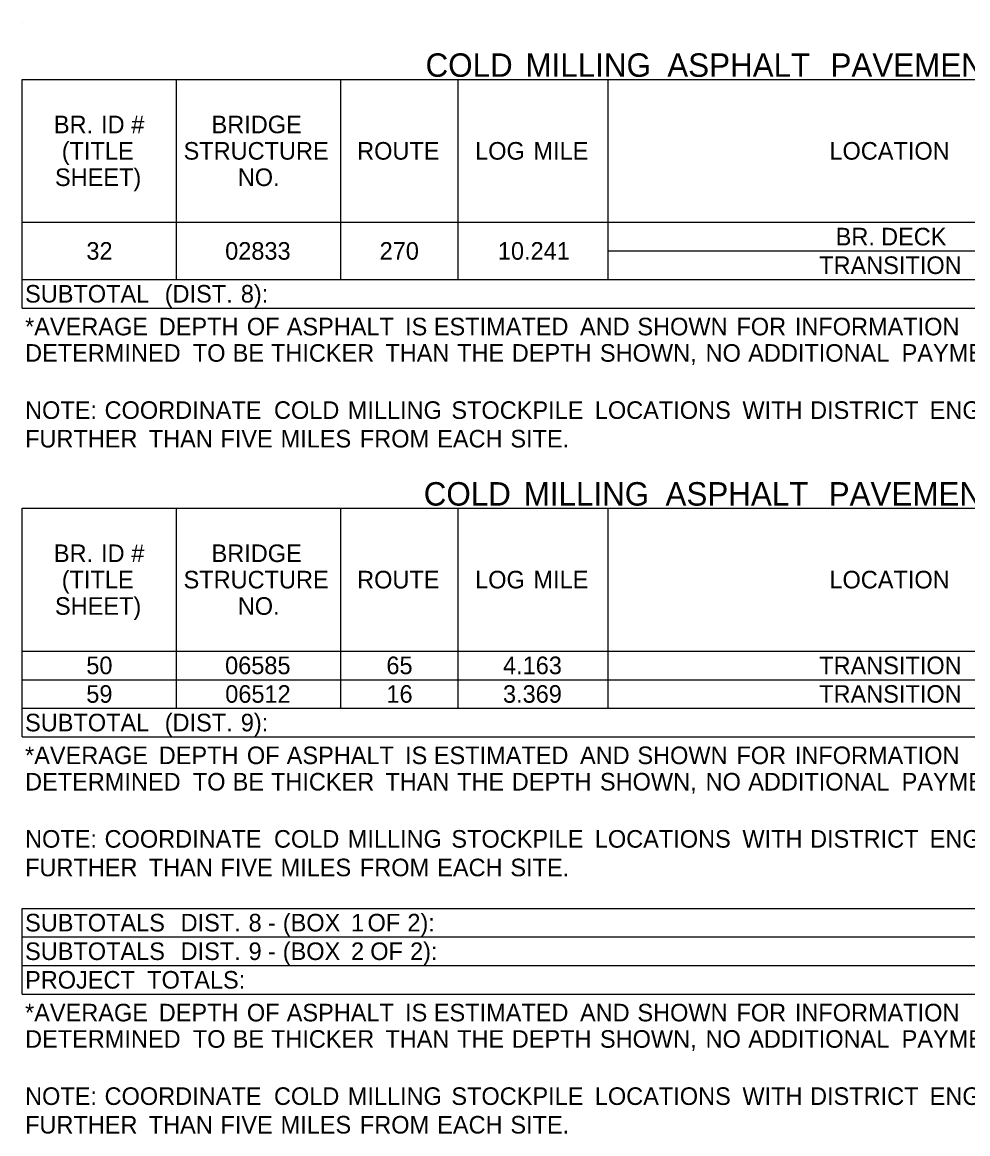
# Model space of a CAD drawing. Extents: x 544420 to 1930787, y -1947044 to 596640.
# Drawn here: x 546578.5 to 546901.1, y -1946424.4 to -1946045.3 of the extents above; entities that cross this region are included whole.
import ezdxf

# ---------------------------------------------------------------- set-up
doc = ezdxf.new("R2010")
doc.units = 0
doc.layers.add('Default', color=7, linetype='Continuous')

msp = doc.modelspace()

# ---------------------------------------------------------------- linework, layer by layer
at = {"layer": 'Default'}
for p, q in [((546578.54, -1946045.29), (546578.54, -1946045.29)), ((546578.54, -1946064.79), (547169.39, -1946064.79)), ((546578.54, -1946064.79), (547169.39, -1946064.79)), ((546578.54, -1946142.79), (546578.54, -1946064.79)), ((546631.19, -1946133.04), (546631.19, -1946064.79)), ((546687.25, -1946133.04), (546687.25, -1946064.79)), ((546727.23, -1946133.04), (546727.23, -1946064.79)), ((546778.41, -1946133.04), (546778.41, -1946064.79)), ((546578.54, -1946113.54), (547169.39, -1946113.54)), ((546578.54, -1946113.54), (546778.41, -1946113.54)), ((546778.41, -1946123.29), (547169.39, -1946123.29)), ((546578.54, -1946133.04), (547169.39, -1946133.04)), ((546578.54, -1946133.04), (547169.39, -1946133.04)), ((546578.54, -1946142.79), (547169.39, -1946142.79)), ((546578.54, -1946211.04), (547169.39, -1946211.04)), ((546578.54, -1946211.04), (547169.39, -1946211.04)), ((546578.54, -1946289.04), (546578.54, -1946211.04)), ((546631.19, -1946279.29), (546631.19, -1946211.04)), ((546687.25, -1946279.29), (546687.25, -1946211.04)), ((546727.23, -1946279.29), (546727.23, -1946211.04)), ((546778.41, -1946279.29), (546778.41, -1946211.04)), ((546578.54, -1946259.79), (547169.39, -1946259.79)), ((546578.54, -1946269.54), (547169.39, -1946269.54)), ((546578.54, -1946279.29), (547169.39, -1946279.29)), ((546578.54, -1946289.04), (547169.39, -1946289.04)), ((546578.54, -1946347.54), (547169.39, -1946347.54)), ((546578.54, -1946347.54), (547169.39, -1946347.54)), ((546578.54, -1946376.79), (546578.54, -1946347.54)), ((546578.54, -1946357.29), (547169.39, -1946357.29)), ((546578.54, -1946367.04), (547169.39, -1946367.04)), ((546578.54, -1946376.79), (547169.39, -1946376.79))]:
    msp.add_line(p, q, dxfattribs=at)

# ---------------------------------------------------------------- texts
for s, height, p in [('COLD', 8, (546716.11, -1946063.91)), (' MILLING', 8, (546747.22, -1946063.91)), (' ASPHALT', 8, (546795.59, -1946063.91)), (' PAVEMENT', 8, (546851.26, -1946063.91)), ('BR.', 6, (546589.34, -1946083.16)), (' ID', 6, (546603.2, -1946083.16)), (' #', 6, (546613.5, -1946083.16)), ('BRIDGE', 6, (546643.12, -1946083.16)), ('(TITLE', 6, (546592.03, -1946092.16)), ('STRUCTURE', 6, (546633.58, -1946092.16)), ('ROUTE', 6, (546692.77, -1946092.16)), ('LOG', 6, (546733.02, -1946092.16)), (' MILE', 6, (546750.68, -1946092.16)), ('LOCATION', 6, (546853.87, -1946092.16)), ('SHEET)', 6, (546589.71, -1946101.16)), ('NO.', 6, (546652.06, -1946101.16)), ('BR.', 6, (546856, -1946121.41)), (' DECK', 6, (546869.25, -1946121.41)), ('32', 6, (546600.43, -1946126.29)), ('02833', 6, (546647.76, -1946126.29)), ('270', 6, (546700.45, -1946126.29)), ('10.241', 6, (546740.78, -1946126.29)), ('TRANSITION', 6, (546850.38, -1946131.16)), ('SUBTOTAL', 6, (546579.51, -1946140.91)), (' (DIST.', 6, (546624.91, -1946140.91)), (' 8):', 6, (546650.87, -1946140.91)), ('*AVERAGE', 6, (546579.51, -1946152.09)), (' DEPTH', 6, (546622.87, -1946152.09)), (' OF', 6, (546652.94, -1946152.09)), (' ASPHALT', 6, (546666.52, -1946152.09)), (' IS', 6, (546706.89, -1946152.09)), (' ESTIMATED', 6, (546716.7, -1946152.09)), (' AND', 6, (546766.56, -1946152.09)), (' SHOWN', 6, (546786.14, -1946152.09)), (' FOR', 6, (546819.92, -1946152.09)), (' INFORMATION', 6, (546839.83, -1946152.09)), ('DETERMINED', 6, (546579.51, -1946161.09)), (' TO', 6, (546634.5, -1946161.09)), (' BE', 6, (546648.09, -1946161.09)), (' THICKER', 6, (546661.16, -1946161.09)), (' THAN', 6, (546700.17, -1946161.09)), (' THE', 6, (546724.64, -1946161.09)), (' DEPTH', 6, (546743.29, -1946161.09)), (' SHOWN,', 6, (546773.36, -1946161.09)), (' NO', 6, (546809.4, -1946161.09)), (' ADDITIONAL', 6, (546823.93, -1946161.09)), (' PAYMENT', 6, (546876.27, -1946161.09)), ('NOTE:', 6, (546579.51, -1946180.59)), (' COORDINATE', 6, (546604.4, -1946180.59)), (' COLD', 6, (546662.18, -1946180.59)), (' MILLING', 6, (546687.35, -1946180.59)), (' STOCKPILE', 6, (546722.69, -1946180.59)), (' LOCATIONS', 6, (546771.62, -1946180.59)), (' WITH', 6, (546821.96, -1946180.59)), (' DISTRICT', 6, (546845.03, -1946180.59)), (' ENGINEER.', 6, (546885.84, -1946180.59)), ('FURTHER', 6, (546579.51, -1946190.34)), (' THAN', 6, (546619.46, -1946190.34)), (' FIVE', 6, (546643.92, -1946190.34)), (' MILES', 6, (546664.44, -1946190.34)), (' FROM', 6, (546691.48, -1946190.34)), (' EACH', 6, (546717.86, -1946190.34)), (' SITE.', 6, (546742.81, -1946190.34)), ('COLD', 8, (546715.49, -1946210.16)), (' MILLING', 8, (546746.61, -1946210.16)), (' ASPHALT', 8, (546794.98, -1946210.16)), (' PAVEMENT', 8, (546850.64, -1946210.16)), ('BR.', 6, (546589.34, -1946229.41)), (' ID', 6, (546603.2, -1946229.41)), (' #', 6, (546613.5, -1946229.41)), ('BRIDGE', 6, (546643.12, -1946229.41)), ('(TITLE', 6, (546592.03, -1946238.41)), ('STRUCTURE', 6, (546633.58, -1946238.41)), ('ROUTE', 6, (546692.77, -1946238.41)), ('LOG', 6, (546733.02, -1946238.41)), (' MILE', 6, (546750.68, -1946238.41)), ('LOCATION', 6, (546853.87, -1946238.41)), ('SHEET)', 6, (546589.71, -1946247.41)), ('NO.', 6, (546652.06, -1946247.41)), ('50', 6, (546600.4, -1946267.66)), ('06585', 6, (546647.74, -1946267.66)), ('65', 6, (546702.75, -1946267.66)), ('4.163', 6, (546742.53, -1946267.66)), ('TRANSITION', 6, (546850.38, -1946267.66)), ('59', 6, (546600.39, -1946277.41)), ('06512', 6, (546647.79, -1946277.41)), ('16', 6, (546702.77, -1946277.41)), ('3.369', 6, (546742.52, -1946277.41)), ('TRANSITION', 6, (546850.38, -1946277.41)), ('SUBTOTAL', 6, (546579.51, -1946287.16)), (' (DIST.', 6, (546624.91, -1946287.16)), (' 9):', 6, (546650.87, -1946287.16)), ('*AVERAGE', 6, (546579.51, -1946298.34)), (' DEPTH', 6, (546622.87, -1946298.34)), (' OF', 6, (546652.94, -1946298.34)), (' ASPHALT', 6, (546666.52, -1946298.34)), (' IS', 6, (546706.89, -1946298.34)), (' ESTIMATED', 6, (546716.7, -1946298.34)), (' AND', 6, (546766.56, -1946298.34)), (' SHOWN', 6, (546786.14, -1946298.34)), (' FOR', 6, (546819.92, -1946298.34)), (' INFORMATION', 6, (546839.83, -1946298.34)), ('DETERMINED', 6, (546579.51, -1946307.34)), (' TO', 6, (546634.5, -1946307.34)), (' BE', 6, (546648.09, -1946307.34)), (' THICKER', 6, (546661.16, -1946307.34)), (' THAN', 6, (546700.17, -1946307.34)), (' THE', 6, (546724.64, -1946307.34)), (' DEPTH', 6, (546743.29, -1946307.34)), (' SHOWN,', 6, (546773.36, -1946307.34)), (' NO', 6, (546809.4, -1946307.34)), (' ADDITIONAL', 6, (546823.93, -1946307.34)), (' PAYMENT', 6, (546876.27, -1946307.34)), ('NOTE:', 6, (546579.51, -1946326.84)), (' COORDINATE', 6, (546604.4, -1946326.84)), (' COLD', 6, (546662.18, -1946326.84)), (' MILLING', 6, (546687.35, -1946326.84)), (' STOCKPILE', 6, (546722.69, -1946326.84)), (' LOCATIONS', 6, (546771.62, -1946326.84)), (' WITH', 6, (546821.96, -1946326.84)), (' DISTRICT', 6, (546845.03, -1946326.84)), (' ENGINEER.', 6, (546885.84, -1946326.84)), ('FURTHER', 6, (546579.51, -1946336.59)), (' THAN', 6, (546619.46, -1946336.59)), (' FIVE', 6, (546643.92, -1946336.59)), (' MILES', 6, (546664.44, -1946336.59)), (' FROM', 6, (546691.48, -1946336.59)), (' EACH', 6, (546717.86, -1946336.59)), (' SITE.', 6, (546742.81, -1946336.59)), ('SUBTOTALS', 6, (546579.51, -1946355.41)), (' DIST.', 6, (546630.34, -1946355.41)), (' 8', 6, (546653.52, -1946355.41)), (' (BOX', 6, (546665.19, -1946355.41)), (' 1', 6, (546688.46, -1946355.41)), (' OF', 6, (546694.09, -1946355.41)), (' 2):', 6, (546707.68, -1946355.41)), (' -', 6, (546660.13, -1946355.41)), ('SUBTOTALS', 6, (546579.51, -1946365.16)), (' DIST.', 6, (546630.34, -1946365.16)), (' 9', 6, (546653.52, -1946365.16)), (' (BOX', 6, (546665.17, -1946365.16)), (' 2', 6, (546688.45, -1946365.16)), (' OF', 6, (546695.02, -1946365.16)), (' 2):', 6, (546708.6, -1946365.16)), (' -', 6, (546660.12, -1946365.16)), ('PROJECT', 6, (546579.51, -1946374.91)), (' TOTALS:', 6, (546618.94, -1946374.91)), ('*AVERAGE', 6, (546579.51, -1946386.09)), (' DEPTH', 6, (546622.87, -1946386.09)), (' OF', 6, (546652.94, -1946386.09)), (' ASPHALT', 6, (546666.52, -1946386.09)), (' IS', 6, (546706.89, -1946386.09)), (' ESTIMATED', 6, (546716.7, -1946386.09)), (' AND', 6, (546766.56, -1946386.09)), (' SHOWN', 6, (546786.14, -1946386.09)), (' FOR', 6, (546819.92, -1946386.09)), (' INFORMATION', 6, (546839.83, -1946386.09)), ('DETERMINED', 6, (546579.51, -1946395.09)), (' TO', 6, (546634.5, -1946395.09)), (' BE', 6, (546648.09, -1946395.09)), (' THICKER', 6, (546661.16, -1946395.09)), (' THAN', 6, (546700.17, -1946395.09)), (' THE', 6, (546724.64, -1946395.09)), (' DEPTH', 6, (546743.29, -1946395.09)), (' SHOWN,', 6, (546773.36, -1946395.09)), (' NO', 6, (546809.4, -1946395.09)), (' ADDITIONAL', 6, (546823.93, -1946395.09)), (' PAYMENT', 6, (546876.27, -1946395.09)), ('NOTE:', 6, (546579.51, -1946414.59)), (' COORDINATE', 6, (546604.4, -1946414.59)), (' COLD', 6, (546662.18, -1946414.59)), (' MILLING', 6, (546687.35, -1946414.59)), (' STOCKPILE', 6, (546722.69, -1946414.59)), (' LOCATIONS', 6, (546771.62, -1946414.59)), (' WITH', 6, (546821.96, -1946414.59)), (' DISTRICT', 6, (546845.03, -1946414.59)), (' ENGINEER.', 6, (546885.84, -1946414.59)), ('FURTHER', 6, (546579.51, -1946424.34)), (' THAN', 6, (546619.46, -1946424.34)), (' FIVE', 6, (546643.92, -1946424.34)), (' MILES', 6, (546664.44, -1946424.34)), (' FROM', 6, (546691.48, -1946424.34)), (' EACH', 6, (546717.86, -1946424.34)), (' SITE.', 6, (546742.81, -1946424.34))]:
    msp.add_text(s, height=height, dxfattribs=at).set_placement(p)

doc.saveas('drawing.dxf')
